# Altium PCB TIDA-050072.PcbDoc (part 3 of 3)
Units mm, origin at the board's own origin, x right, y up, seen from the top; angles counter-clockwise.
Board outline 125.73 x 87.63 mm, 2 copper layers (Top Layer, Bottom Layer), stack 1.575 mm thick; 105 components, 63 nets, 347 pads, 390 vias.
Unrouted connection lines stored in the file: 6.
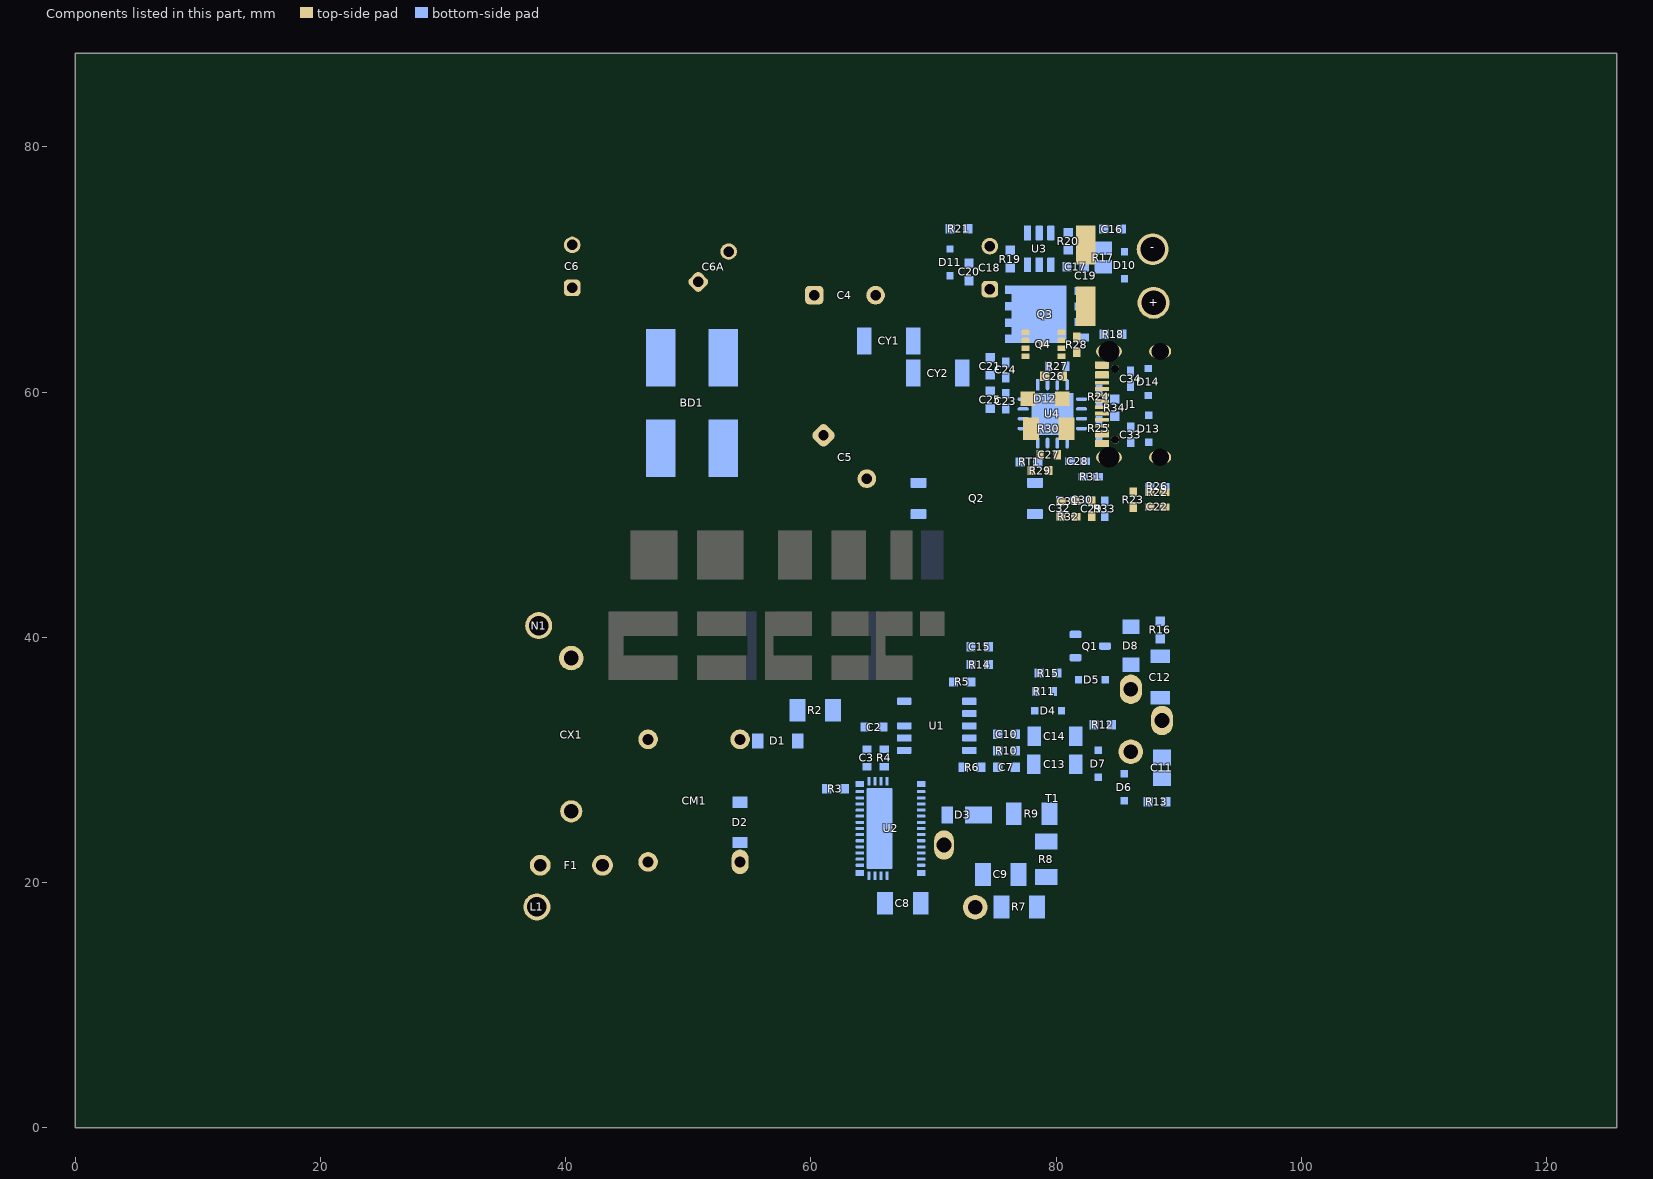
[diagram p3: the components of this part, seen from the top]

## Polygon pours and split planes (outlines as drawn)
NetBD1_3 on Top Layer "TOP_LAYER_NETBD1_3_P046" (solid, remove dead copper, pour order 46): 54.5,55.375 54.029,55.846 51.171,55.846 50.7,55.375 50.7,44.713 54.5,44.712
NetBD1_2 on Top Layer "TOP_LAYER_NETBD1_2_P048" (solid, remove dead copper, pour order 48): 49.1,55.4 48.654,55.846 45.746,55.846 45.275,55.375 45.275,44.7 49.1,44.7
NetBD1_1 on Top Layer "TOP_LAYER_NETBD1_1_P050" (solid, remove dead copper, pour order 50): 51.025,69.95 46.95,69.95 46.3,69.3 36.7,69.3 36.2,68.8 36.2,66.35 36.675,65.875 45,65.875 45.3,65.575 45.3,58.125 45.95,57.475 48.602,57.475 48.95,57.823 48.95,65.325 48.975,65.325 51.9,68.25 51.9,69.1 51.05,69.95
NetBD1_1 on Top Layer "TOP_LAYER_NETBD1_1_P052" (solid, remove dead copper, pour order 52): 58.925,69.1 60.607,69.1 61.4,68.307 61.4,57.925 62,57.325 62,56.166 60.1,54.266 60.1,44.712 57.325,44.712 57.3,44.738 57.3,55.75 58.375,56.825 58.375,65.462 58.375,68.55
G on Top Layer "TOP_LAYER_G_P056" (solid, remove dead copper, pour order 56): 56.75,58.05 56.175,57.475 51.975,57.475 51.625,57.825 51.625,65.725 53.475,67.575 53.475,69.8 51.75,71.525 45.5,71.525 44.85,70.875 36.775,70.875 36.25,71.4 36.25,73.85 36.7,74.3 68.25,74.3 69.1,73.45 69.1,67.8 67.3,66 67.3,51.95 64.5,49.15 64.5,44.712 61.682,44.712 61.682,53.557 63.625,55.5 63.625,58.05 63,58.675 63,68.9 61.225,70.675 58.275,70.675 56.75,69.15
Vo on Top Layer "TOP_LAYER_VO_P057" (solid, remove dead copper, pour order 57): 74.575,69.625 77.65,69.625 78.3,68.975 83.554,68.975 84.815,67.714 84.815,65.4 79.79,65.4 79.475,65.085 79.475,62.35 79.295,62.17 77.53,62.17 73.75,65.95 73.75,68.8
VBUS on Top Layer "TOP_LAYER_VBUS_P058" (solid, remove dead copper, pour order 58): 80.1,64.425 80.1,58.95 80.25,58.8 81.21,58.8 81.8,58.21 81.8,57 82.5,56.3 84.225,56.3 84.225,56.9 83.11,56.9 82.95,57.06 82.95,60.925 83.125,61.1 84.25,61.1 84.25,61.701 83.024,61.701 82.85,61.875 82.85,62.475 82.725,62.6 82.3,62.6 81.975,62.925 81.975,63.5 81.375,63.5 80.775,64.1 80.775,64.425
SGND on Top Layer "TOP_LAYER_SGND_P059" (solid, remove dead copper, pour order 59): 85.075,74.15 71.35,74.15 70.35,73.15 70.35,66.1 74.3,62.15 74.3,60.725 75.525,59.5 75.525,57.875 77.325,56.075 78.675,56.075 78.675,58.075 78.35,58.4 78.35,59.825 79.45,60.925 79.45,61.675 77.35,61.675 73.375,65.65 73.375,69.275 74.175,70.075 84.525,70.075 85.025,69.575 88.7,69.575 89.3,70.175 89.3,72.5 88.625,73.175 86.925,73.175 86.425,72.675 85.9,72.675 85.425,73.15 85.425,73.825 85.4,73.825
RTN on Top Layer "TOP_LAYER_RTN_P063" (solid, remove dead copper, pour order 63): 83.175,62.029 83.175,63.869 83.637,64.331 84.956,64.331 85.862,63.425 86.441,63.425 86.75,63.116 86.75,62.675 87.422,62.003 88.984,62.003 89.265,61.723 89.265,56.3 89.037,56.072 87.5,56.072 86.675,55.247 86.675,53.919 87.25,53.344 87.25,52.711 87.014,52.475 84.112,52.475 83.791,52.797 83.791,53.801 83.441,54.15 82.125,54.15 80.481,55.794 80.481,57.925 81.495,57.925 81.495,56.926 82.321,56.1 84.357,56.1 84.8,56.543 84.8,61.615 84.515,61.9 83.304,61.9
G on Top Layer "TOP_LAYER_G_P028" (solid, remove dead copper, pour order 28): 61.7,38.5 61.7,35.85 58.35,32.5 57.225,32.5 56.6,31.875 56.6,20.65 57.5,19.75 66.693,19.75 68.575,21.632 68.575,27.066 67.916,27.725 64.75,27.725 64.55,27.525 64.55,25.75 64.15,25.35 60.6,25.35 60.6,29.675 65.225,34.3 65.225,35.95 64.7,36.475 64.7,38.5
G on Top Layer "TOP_LAYER_G_P073" (solid, remove dead copper, pour order 73): 68.45,24.349 68.58,24.479 68.58,27.94 68.07,28.45 67.035,28.45 66.17,27.585 66.17,25.32 67.141,24.349
G on Top Layer "TOP_LAYER_G_P067" (solid, remove dead copper, pour order 67): 72.5,40.3 72.5,37.692 69.758,34.95 66.9,34.95 63.475,31.525 61.615,29.665 61.615,26.232 62.05,25.797 63.742,25.8 64.15,26.208 64.15,27.7 64.675,28.225 65.95,28.225 66.575,28.85 69.95,28.85 70.753,28.047 82.528,28.047 87.375,23.2 88.75,23.2 89.675,24.125 89.675,28.952 87.25,31.377 87.25,39.925 85.95,41.225 73.425,41.225
NetD3_1 on Top Layer "TOP_LAYER_NETD3_1_P066" (solid, remove dead copper, pour order 66): 72.912,26.537 81.538,26.537 85.95,22.125 85.95,19.108 83.804,16.962 78.063,16.962 73,22.025 73,24.375 72.575,24.8 72.575,26.2
NetBD1_1 on Top Layer "TOP_LAYER_NETBD1_1_P016" (solid, remove dead copper, pour order 16): 56.25,37.536 56.25,35.4 55.8,34.95 49.85,34.95 49.1,34.2 49.1,17.65 50,16.75 71.525,16.75 71.95,17.175 71.95,18.8 71.525,19.225 68.325,19.225 67.35,18.25 54.15,18.25 51.85,20.55 51.85,33.3 52.6,34.05 57.65,34.05 60.1,36.5 60.1,37.536
NetCM1_1 on Top Layer "TOP_LAYER_NETCM1_1_P014" (solid, remove dead copper, pour order 14): 46.7,28.8 47.55,27.95 47.55,20.55 47,20 45.8,20 45.3,20.5 45.3,25.4 44.45,26.25 42,26.25 41.8,26.05 41.8,25.7 42,25.5 44,25.5 44.45,25.05 44.45,20.9 43.8,20.25 42.45,20.25 42.1,20.6 42.1,22.9 39.2,25.8 39.2,28.05 39.95,28.8
NetF1_2 on Top Layer "TOP_LAYER_NETF1_2_P012" (solid, remove dead copper, pour order 12): 39,21.55 38.05,22.5 36.75,22.5 36.2,21.95 36.2,17.25 36.65,16.8 38.6,16.8 39,17.2
NetCM1_2 on Top Layer "TOP_LAYER_NETCM1_2_P008" (solid, remove dead copper, pour order 8): 40.6,42.15 41.75,41 41.75,34.95 42.65,34.05 46.75,34.05 47.55,33.25 47.55,31.25 46.8,30.5 37.85,30.5 36.55,31.8 36.55,35.8 38.3,37.55 38.3,38.5 36.4,40.4 36.4,41.65 36.9,42.15
NetBD1_2 on Bottom Layer "BOTTOM_LAYER_NETBD1_2_P030" (solid, remove dead copper, pour order 30): 49.1,55.4 48.654,55.846 45.746,55.846 45.275,55.375 45.275,44.7 49.1,44.7
NetBD1_3 on Bottom Layer "BOTTOM_LAYER_NETBD1_3_P032" (solid, remove dead copper, pour order 32): 54.5,55.375 54.029,55.846 51.171,55.846 50.7,55.375 50.7,44.713 54.5,44.712
G on Bottom Layer "BOTTOM_LAYER_G_P034" (solid, remove dead copper, pour order 34): 51.65,57.475 51.65,64.325 52.375,65.05 55.925,65.05 56.8,64.175 56.8,58.1 56.175,57.475
NetBD1_1 on Bottom Layer "BOTTOM_LAYER_NETBD1_1_P036" (solid, remove dead copper, pour order 36): 48.95,57.45 45.975,57.45 45.3,58.125 45.3,61.15 45.3,65.575 45,65.875 36.675,65.875 36.2,66.35 36.2,68.8 36.7,69.3 46.3,69.3 46.95,69.95 51.05,69.95 51.9,69.1 58.55,69.1 60.95,69.1 62,68.05 62,56.166 60.1,54.266 60.1,44.712 57.325,44.712 57.3,44.738 57.3,55.75 58.375,56.825 58.375,65.375 57.1,66.65 50.275,66.65 48.95,65.325
G on Bottom Layer "BOTTOM_LAYER_G_P038" (solid, remove dead copper, pour order 38): 61.682,53.557 63.6,55.475 63.6,68.757 61.682,70.675 52.6,70.675 51.75,71.525 46.325,71.525 45.675,70.875 36.775,70.875 36.25,71.4 36.25,73.85 36.7,74.3 68.25,74.3 69.1,73.45 69.1,70.475 64.925,66.3 64.925,59.3 65.575,58.65 65.575,50.225 64.5,49.15 64.5,44.712 61.682,44.712
RTN on Bottom Layer "BOTTOM_LAYER_RTN_P060" (solid, remove dead copper, pour order 60): 83.275,63.675 83.275,61.361 83.661,60.975 85.325,60.975 85.64,61.29 87.26,61.29 88.2,60.35 88.2,57.375 87.125,56.3 85.8,56.3 85.1,55.6 83.525,55.6 83.2,55.275 83.2,54.472 83.807,53.865 89.19,53.865 89.75,54.425 89.75,64.275 89.275,64.75 87.35,64.75 86.6,64 83.6,64
Net+_1 on Bottom Layer "BOTTOM_LAYER_NET+_1_P061" (solid, remove dead copper, pour order 61): 83.25,70.139 86.661,70.139 87,69.8 88.825,69.8 89.375,69.25 89.375,66.15 88.89,65.665 83.015,65.665 82.725,65.375 81.525,65.375 81.525,68.575 82.75,68.575 83.25,69.075
Vo on Bottom Layer "BOTTOM_LAYER_VO_P062" (solid, remove dead copper, pour order 62): 80.85,68.7 75.975,68.7 75.2,69.475 72.9,69.475 72.9,65.175 74.311,63.764 80.614,63.764 80.85,64
SGND on Bottom Layer "BOTTOM_LAYER_SGND_P064" (solid, remove dead copper, pour order 64): 74.925,72.775 73.775,72.775 72.525,71.525 72.525,70.139 74.953,70.139 75.4,70.586 75.4,72.3
G on Bottom Layer "BOTTOM_LAYER_G_P072" (solid, remove dead copper, pour order 72): 75.785,41.975 84.439,41.975 85.025,41.389 85.025,37.5 86.95,35.575 86.95,34.063 86.662,33.775 83.141,33.775 79.603,37.313 78.925,37.313 76.562,34.95 75.975,34.95 75.161,35.764 75.161,41.351
G on Bottom Layer "BOTTOM_LAYER_G_P071" (solid, remove dead copper, pour order 71): 66.925,36.525 68.51,36.525 68.975,36.06 69.575,35.459 69.575,30.666 69.966,30.275 70.984,30.275 71.95,31.262 71.95,32.868 70.775,34.043 70.775,35.089 70.775,36.994 71.094,37.313 72.148,37.313 72.7,36.761 72.7,36.06 73.45,36.06 73.45,40.886 73.186,41.15 71.75,41.15 71.35,40.75 71.35,38.533 71.194,38.378 66.925,38.378
NetF1_2 on Bottom Layer "BOTTOM_LAYER_NETF1_2_P068" (solid, remove dead copper, pour order 68): 39,21.55 38.05,22.5 36.75,22.5 36.2,21.95 36.2,17.25 36.65,16.8 38.6,16.8 39,17.2
NetCM1_1 on Bottom Layer "BOTTOM_LAYER_NETCM1_1_P069" (solid, remove dead copper, pour order 69): 46.7,28.8 47.55,27.95 47.55,20.55 47,20 45.8,20 45.3,20.5 45.3,25.4 44.45,26.25 42,26.25 41.8,26.05 41.8,25.7 42,25.5 44,25.5 44.45,25.05 44.45,20.9 43.8,20.25 42.45,20.25 42.1,20.6 42.1,22.9 39.2,25.8 39.2,28.05 39.95,28.8
NetCM1_2 on Bottom Layer "BOTTOM_LAYER_NETCM1_2_P070" (solid, remove dead copper, pour order 70): 40.6,42.15 41.75,41 41.75,35.25 44.125,32.875 46.9,32.875 47.55,32.225 47.55,31.25 46.8,30.5 37.85,30.5 36.55,31.8 36.55,35.8 38.3,37.55 38.3,38.5 36.4,40.4 36.4,41.65 36.9,42.15
G on Bottom Layer "BOTTOM_LAYER_G_P065" (solid, remove dead copper, pour order 65): 76.275,29.025 76.525,28.775 79.875,28.775 80.5,29.4 80.5,31.675 78.85,33.325 77.025,33.325 76.275,32.575
NetBD1_1 on Bottom Layer "BOTTOM_LAYER_NETBD1_1_P026" (solid, remove dead copper, pour order 26): 71.225,19.225 73.35,21.35 74.65,21.35 74.675,21.325 74.675,19.625 75.475,18.825 75.475,17.075 75.15,16.75 68.75,16.75 68.325,17.175 68.325,18.975 68.575,19.225
NetD3_1 on Bottom Layer "BOTTOM_LAYER_NETD3_1_P020" (solid, remove dead copper, pour order 20): 72.575,26.2 72.575,24.8 73,24.375 73,23.05 73.4,22.65 76.8,22.65 77.187,23.038 77.188,26.537 72.912,26.537
NetD3_2 on Bottom Layer "BOTTOM_LAYER_NETD3_2_P018" (solid, remove dead copper, pour order 18): 71.575,26.199 69.892,26.208 69.5,26.6 69.5,27.325 69.3,27.525 68.725,27.525 68.65,27.45 68.65,21.35 68.725,21.275 70.775,21.275 71.575,22.075
G on Bottom Layer "BOTTOM_LAYER_G_P006" (solid, remove dead copper, pour order 6): 60.25,25.5 59.8,25.95 59.8,26.9 59.575,27.125 57.75,27.125 57.15,26.525 57.15,18.125 57.875,17.4 64.725,17.4 65.186,17.861 66.65,17.861 66.65,27.661 64.55,27.661 64.55,25.6 64.45,25.5
NetBD1_3 on Bottom Layer "BOTTOM_LAYER_NETBD1_3_P004" (solid, remove dead copper, pour order 4): 50.7,37.6 50.7,36.461 53.4,33.761 53.4,31.2 53.95,30.65 55.8,30.65 56.1,30.95 56.1,32.6 55.55,33.15 55.55,37.6
NetBD1_2 on Bottom Layer "BOTTOM_LAYER_NETBD1_2_P002" (solid, remove dead copper, pour order 2): 43.5,35.9 44.95,34.45 47.5,34.45 49.4,32.55 49.4,22.325 51.563,20.162 54.362,20.162 54.95,20.75 54.95,23.65 54.55,24.05 53.1,24.05 51.8,25.35 51.8,26.55 51.8,33.05 49.1,35.75 49.1,38.2 43.5,38.2

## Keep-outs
Keep-Out Layer:
  text ".Layer_Name" at 14.656,-21.806 h1.52

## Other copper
Top Layer:
  text ".Layer_Name" at 14.656,-21.806 h1.52
Bottom Layer:
  text ".Layer_Name" at 14.656,-21.806 h1.52

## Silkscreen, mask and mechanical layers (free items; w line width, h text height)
Top Overlay:
  text ".Layer_Name" at 14.656,-21.806 h1.52
Bottom Overlay:
  lines w0.2: 75.375,39.3 75.375,41.275 76.225,42.125 89.05,42.125 89.65,41.525 89.65,38 ; 65.8,54.325 65.8,59.863 71.469,59.863 71.469,54.311 65.814,54.311 65.8,54.325
  text "**" at 89.544,60.78 h0.8 r90
  text "**" at 71.471,58.212 h0.8 r90
  text ".Layer_Name" at 14.656,-21.806 h1.52
Top Paste:
  text ".Layer_Name" at 14.656,-21.806 h1.52
Bottom Paste:
  text ".Layer_Name" at 14.656,-21.806 h1.52
Top Solder:
  text ".Layer_Name" at 14.656,-21.806 h1.52
  text ".Layer_Name" at 14.656,-21.806 h1.52
Bottom Solder:
  text ".Layer_Name" at 14.656,-21.806 h1.52
Drill Guide:
  text ".Layer_Name" at 14.656,-21.806 h1.52
M1 Board Outline:
  circle w0.15: c91,36 r1
  circle w0.15: c91,25.5 r1
  circle w0.15: c76,15.5 r1
  circle w0.15: c54,15.5 r1
  circle w0.15: c35,24 r1
  circle w0.15: c35,35 r1
  circle w0.15: c69.5,43.5 r1
  circle w0.15: c91,52 r1
  circle w0.15: c91,69 r1
  circle w0.15: c35,67 r1
  circle w0.15: c73,75.5 r1
  circle w0.15: c58,75.5 r1
  circle w0.15: c60.9,43.5 r1
  circle w0.15: c49.9,43.5 r1
  lines w0.15: 35.994,16.5 90,16.5 90,42.5 35.994,42.5 ; 36,16.5 36,42.5 ; 36,65.5 45,65.5 45,44.5 54.7,44.5 54.7,48 57.1,48 57.1,44.5 64.7,44.5 64.7,48 66.3,48 66.3,44.5 71,44.5 71,49 90,49 90,74.5 70.2,74.5 70.2,64 69.4,64 69.4,74.5 36,74.5 36,65.5 ; 44.8,38.6 44.8,40 54.8,40 54.8,38.6 44.8,38.6 ; 57,38.6 64.8,38.6 64.8,40 57,40 57,38.6 ; 66.2,38.6 71.1,38.6 71.1,40 66.2,40 66.2,38.6
  lines w0.254: 0.125,0 0.125,87.63 125.73,87.63 125.73,0 0.125,0
  text ".Layer_Name" at 14.656,-21.806 h1.52
M2 Board Dimensions:
  rectangle: 0,-6.985 3.175,-3.81
  rectangle: 3.175,-10.16 12.7,-6.985
  lines w0.178: 0,-6.985 25.4,-6.985 ; 3.175,-10.16 3.175,-3.81 ; 6.35,-10.16 6.35,-3.81 ; 12.7,-10.16 12.7,-3.81 ; 19.05,-10.16 19.05,-3.81 ; 0,-10.16 25.4,-10.16 25.4,-3.81 0,-3.81 0,-10.16
  text ".Layer_Name" at 14.656,-21.806 h1.52
M3 3D STEP Top:
  text ".Layer_Name" at 14.656,-21.806 h1.52
M4 3D STEP Bottom:
  text ".Layer_Name" at 14.656,-21.806 h1.52
M5 Assembly Top:
  lines w0.254: -7.417,-23.626 160.223,-23.626 ; -7.417,-18.462 160.274,-18.462 ; -7.417,-13.297 -7.417,-28.791 94.31,-28.791 160.274,-28.791 160.274,-13.297 -7.404,-13.297 -7.404,-28.791 32.614,-28.791 ; 55.194,-28.791 55.194,-13.297 ; 87.376,-18.462 87.376,-13.297 ; 108.712,-18.462 108.712,-13.297 ; 124.511,-28.956 124.511,-23.804
  text "COMPONENTS MARKED 'DNP' SHOULD NOT BE POPULATED." at 29.299,-8.09 h1.52
  text "ASSEMBLY VARIANT:" at 29.286,-11.024 h1.52
  text ".VariantName" at 55.601,-11.024 h1.52
  text "PCB VIEWED FROM TOP SIDE" at -5.804,-16.654 h1.52
  text "BOARD #:" at 57.099,-16.654 h1.52
  text ".PRJ_Number" at 70.955,-16.654 h1.52
  text "REV:" at 92.405,-16.654 h1.52
  text ".PCB_Rev" at 99.809,-16.654 h1.52
  text "SVN REV:" at 113.69,-16.654 h1.52
  text ".VersionControl_RevNumber" at 126.543,-16.654 h1.52
  text "TID #:" at 57.099,-21.819 h1.52
  text ".TID" at 70.955,-21.819 h1.52
  text "PLOT NAME =" at -5.804,-27.034 h1.52
  text ".plot_File_Name" at 14.656,-27.034 h1.52
  text "GENERATED    :" at 57.15,-27.034 h1.52
  text ".Print_Date" at 79.235,-27.034 h1.52
  text ".Print_Time" at 97.752,-27.034 h1.52
  text "TEXAS INSTRUMENTS" at 129.87,-27.034 h1.52
M6 Assembly Bottom:
  lines w0.254: -7.429,-18.474 160.261,-18.474 ; -7.379,-23.639 160.261,-23.639 ; 28.334,-28.969 28.334,-23.817 ; 44.133,-18.474 44.133,-13.31 ; 65.468,-18.474 65.468,-13.31 ; 97.65,-28.804 97.65,-13.31 ; 120.231,-28.804 160.249,-28.804 160.249,-13.31 -7.429,-13.31 -7.429,-28.804 58.534,-28.804 160.261,-28.804 160.261,-13.31
  text "COMPONENTS MARKED 'DNP' SHOULD NOT BE POPULATED." at 154.991,-8.077 h1.52
  text ".VariantName" at 128.473,-11.024 h1.52
  text "ASSEMBLY VARIANT:" at 154.864,-11.024 h1.52
  text ".VersionControl_RevNumber" at 26.302,-16.667 h1.52
  text "SVN REV:" at 39.154,-16.667 h1.52
  text ".PCB_Rev" at 53.035,-16.667 h1.52
  text "REV:" at 60.439,-16.667 h1.52
  text ".PRJ_Number" at 81.89,-16.667 h1.52
  text "BOARD #:" at 95.745,-16.667 h1.52
  text "PCB VIEWED FROM BOTTOM SIDE" at 158.648,-16.667 h1.52
  text ".TID" at 81.89,-21.831 h1.52
  text "TID #:" at 95.745,-21.831 h1.52
  text "TEXAS INSTRUMENTS" at 22.974,-27.047 h1.52
  text ".Print_Time" at 55.093,-27.047 h1.52
  text ".Print_Date" at 73.609,-27.047 h1.52
  text "GENERATED    :" at 95.694,-27.047 h1.52
  text ".plot_File_Name" at 138.189,-27.047 h1.52
  text "PLOT NAME =" at 158.648,-27.047 h1.52
M9 Title Sheet:
  drawing of 57 lines, arcs and shapes, not listed
  text "1" at 18.792,204.127 h1.78
  text "2" at 82.182,204.127 h1.78
  text "3" at 145.411,204.127 h1.78
  text "4" at 209.08,204.127 h1.78
  text "5" at 272.555,204.127 h1.78
  text "6" at 336.182,204.127 h1.78
  text "A" at -10.579,175.095 h1.78
  text "A" at 365.341,175.095 h1.78
  text "B" at -10.579,114.643 h1.78
  text "B" at 365.341,114.643 h1.78
  text "C" at -10.579,54.318 h1.78
  text "C" at 365.341,54.318 h1.78
  text "PROJECT TITLE:" at 288.125,7.048 h1.14
  text ".PRJ_Title" at 289.395,3.662 h1.78
  text "DESIGNED FOR:" at 288.125,-0.597 h1.14
  text ".PRJ_Customer" at 289.395,-4.153 h1.78
  text "D" at -10.579,-5.88 h1.78
  text "D" at 365.341,-5.88 h1.78
  text "FILE NAME:" at 288.125,-8.217 h1.14
  text ".PCB_File_Name_No_Path" at 289.395,-11.265 h1.78
  text "Texas Instruments (TI) and/or its licensors do not warrant the accuracy or completeness of this specification" at 161.9,-15.376 h1.14
  text "ENGINEER:" at 288.125,-15.583 h1.14
  text "LAYOUT BY:" at 326.352,-15.583 h1.14
  text "or any information contained therein. TI and/or its licensors do not warrant that this design will meet" at 160.757,-18.237 h1.14
  text ".PRJ_Engineer" at 289.395,-19.52 h1.78
  text ".PCB_Layout" at 327.635,-19.52 h1.78
  text "the specifications, will be suitable for your application or fit for any particular purpose, or will operate in" at 160.757,-21.099 h1.14
  text ".Layer_Name" at 14.656,-21.806 h1.52
  text "ALTIUM DESIGNER VERSION:" at 326.352,-23.457 h1.14
  text "an implementation. TI and/or its licensors do not warrant that the design is production worthy. You should" at 160.757,-23.961 h1.14
  text "completely validate and test your design implementation to confirm the system functionality for your application." at 161.9,-26.822 h1.14
  text ".print_Scale" at 289.395,-26.843 h1.78
  text ".Application_BuildNumber" at 327.635,-26.843 h1.78
  text "1" at 18.792,-32.093 h1.78
  text "2" at 82.182,-32.093 h1.78
  text "3" at 145.411,-32.093 h1.78
  text "4" at 209.08,-32.093 h1.78
  text "5" at 272.555,-32.093 h1.78
  text "6" at 336.182,-32.093 h1.78
M10 Fab Notes:
  drawing of 189 lines, arcs and shapes, not listed
  text "DESIGN INFORMATION" at 314.503,161.447 h1.52
  text "MIN. TRACK WIDTH:" at 298.131,158.091 h1.52
  text "8" at 325.976,158.091 h1.52
  text "MIL" at 329.907,158.091 h1.52
  text "7.874" at 321.75,155 h1.52
  text "MIN. CLEARANCE:" at 298.131,154.938 h1.52
  text "MIL" at 329.907,154.938 h1.52
  text "MIN. VIA PAD SIZE:" at 298.131,151.785 h1.52
  text "24" at 325.214,151.785 h1.52
  text "MIL" at 329.907,151.785 h1.52
  text "0.05mm (2MIL)" at 315.784,148.486 h1.52
  text "MINIMUM ANNULAR RING" at 289.769,148.277 h1.52
  text "EXTERNAL" at 333.768,148.277 h1.52
  text "PER" at 294.849,145.48 h1.52
  text "IPC-D-275 CLASS 2 LEVEL C" at 300.437,145.48 h1.52
  text "MIL, HOLES" at 338.238,142.928 h1.52
  text "+/-" at 328.27,142.709 h1.52
  text "+/-" at 349.961,142.709 h1.52
  text "REGISTRATION TOLERANCES:" at 289.769,142.682 h1.52
  text "METAL" at 320.243,142.682 h1.52
  text "5" at 334.879,142.683 h1.52
  text "3" at 356.037,142.683 h1.52
  text "MIL" at 358.99,142.682 h1.52
  text "HOLE SIZE TOLERANCE (UNLESS OTHERWISE SPECIFIED):" at 289.769,140.185 h1.52
  text "+/-" at 349.961,140.112 h1.52
  text "3" at 356.037,140.085 h1.52
  text "MIL" at 358.99,140.085 h1.52
  text "MATERIAL:" at 287.87,136.589 h1.52
  text "FR-4 High Tg" at 312.926,133.324 h1.52
  text "X" at 309.257,133.122 h1.52
  text "FR-408" at 298.563,133.007 h1.52
  text "OTHER" at 336.358,133.007 h1.52
  text "62 MIL (1.6mm) +/-10%" at 306.694,129.374 h1.52
  text "X" at 303.643,129.312 h1.52
  text "THICKNESS:" at 289.769,129.165 h1.52
  text "OTHER" at 339.33,129.165 h1.52
  text "TOLERANCE:" at 289.769,125.652 h1.52
  text "X" at 311.314,125.652 h1.52
  text "ANSI IPC-6012 TYPE 3 CLASS 2" at 315.836,125.652 h1.52
  text "OTHER +/-" at 315.835,121.989 h1.52
  text "BOW & TWIST:" at 289.769,118.302 h1.52
  text "X" at 311.314,118.302 h1.52
  text "ANSI IPC-6012 TYPE 3 CLASS 2" at 315.836,118.302 h1.52
  text "OTHER +/-" at 315.835,114.576 h1.52
  text "DRILLING:" at 287.87,111.258 h1.52
  text "NC_DRILL FILES" at 332.599,108.586 h1.52
  text "REFERENCE:" at 289.769,108.486 h1.52
  text "X" at 306.463,108.484 h1.52
  text "AS SHOWN" at 310.984,108.486 h1.52
  text "X" at 329.348,108.486 h1.52
  text "OTHER" at 340.168,104.873 h1.52
  text "PTH COPPER THICKNESS:" at 289.761,104.783 h1.52
  text "X" at 318.697,104.783 h1.52
  text "20-30 um" at 321.948,104.783 h1.52
  text "BOARD FINISH:" at 287.87,101.034 h1.52
  text "SILKSCREEN:" at 291.812,98.237 h1.52
  text "X" at 316.14,98.237 h1.52
  text "TOP" at 319.112,98.237 h1.52
  text "X" at 329.094,98.237 h1.52
  text "BOTTOM" at 332.091,98.237 h1.52
  text "SILKSCREEN COLOR:" at 291.812,94.295 h1.52
  text "X" at 316.115,94.295 h1.52
  text "WHITE" at 319.112,94.295 h1.52
  text "OTHER" at 332.091,94.295 h1.52
  text "X" at 319.442,90.652 h1.52
  text "GREEN" at 322.439,90.652 h1.52
  text "OTHER" at 338.136,90.652 h1.52
  text "SOLDER RESIST COLOR:" at 291.812,90.477 h1.52
  text "X" at 319.442,86.734 h1.52
  text "MATTE" at 322.439,86.734 h1.52
  text "SEMI-GLOSS" at 338.125,86.717 h1.52
  text "IMMERSION GOLD (ENIG)" at 314.819,82.345 h1.52
  text "ENEPIG" at 348.793,82.162 h1.52
  text "SURFACE FINISH:" at 287.87,82.136 h1.52
  text "X" at 310.298,82.136 h1.52
  text "IMM. TIN/SILVER OR EQUIV" at 296.24,78.649 h1.52
  text "OTHER" at 332.599,78.549 h1.52
  text "ARRAY/PANEL:" at 287.87,74.602 h1.52
  text "CUT AND TRIM PER M1 BOARD OUTLINE" at 314.819,74.393 h1.52
  text "N.C. ROUTE" at 314.819,70.94 h1.52
  text "X" at 332.295,70.94 h1.52
  text "V. SCORE" at 336.816,70.94 h1.52
  text "CERTIFICATION:" at 287.87,67.66 h1.52
  text "MATERIALS AND WORKMANSHIP FOR ALL PCBS" at 306.285,67.66 h1.52
  text "TO MEET OR EXCEED THE REQUIREMENTS OF:" at 306.285,65.271 h1.52
  text "X" at 297.078,62.003 h1.52
  text "ANSI IPC-A-600F CLASS ->" at 300.329,62.003 h1.52
  text "X" at 342.188,62.003 h1.52
  text "2" at 344.982,62.003 h1.52
  text "1" at 336.981,61.965 h1.52
  text "3" at 353.973,61.965 h1.52
  text "X" at 317.702,58.252 h1.52
  text "RoHS" at 320.953,58.252 h1.52
  text "OTHER" at 337.321,58.252 h1.52
  text "PER ORDER" at 347.407,58.252 h1.52
  text "ALL BOARDS MUST MEET OR EXCEED UL94-V0 REQUIREMENTS." at 288.569,54.345 h1.52
  text "PCB MUST BEAR THE UL94V-0 UL REGISTERED MATERIAL ID NUMBER" at 288.569,51.397 h1.52
  text "ADDITIONAL REQUIREMENTS:" at 287.87,47.094 h1.52
  text "MICROSECTION:" at 289.769,44.373 h1.52
  text "YES" at 312.775,44.373 h1.52
  text "REQUIRED" at 334.657,40.707 h1.52
  text "BARE BOARD ELEC. TEST:" at 289.769,40.634 h1.52
  text "NONE" at 322.935,40.634 h1.52
  text "X" at 331.66,40.634 h1.52
  text "PER ORDER" at 349.693,40.634 h1.52
  text "XX MIL VIAS REQUIRE NON-CONDUCTIVE FILL AND PLANARIZE" at 294.04,35.428 h1.5
  text "XX MIL VIAS REQUIRE CONDUCTIVE FILL AND PLANARIZE" at 294.243,32.787 h1.52
  text "OUTER XX MIL TRACES REQUIRE 50 OHM SINGLE-ENDED IMPEDANCE" at 294.218,28.637 h1.47
  text "LAYER 2 & 3 (INNER LAYERS) XX MIL WIDE, XX MIL SPACE / TRACES REQUIRE 100 OHM DIFFERENTIAL IMPEDANCE" at 294.015,22.65 h1.52
  text ".Layer_Name" at 14.656,-21.806 h1.52
M11 Gerber Information:
  lines w0.254: -7.417,-23.626 160.223,-23.626 ; -7.417,-18.462 160.274,-18.462 ; -7.417,-13.297 -7.417,-28.791 94.31,-28.791 160.274,-28.791 160.274,-13.297 -7.404,-13.297 -7.404,-28.791 32.614,-28.791 ; 55.194,-28.791 55.194,-13.297 ; 87.376,-18.462 87.376,-13.297 ; 108.712,-18.462 108.712,-13.297 ; 124.511,-28.956 124.511,-23.804
  text "ALL ARTWORK VIEWED FROM TOP SIDE" at -5.804,-16.654 h1.52
  text "BOARD #:" at 57.099,-16.654 h1.52
  text ".PRJ_Number" at 70.955,-16.654 h1.52
  text "REV:" at 92.405,-16.654 h1.52
  text ".PCB_Rev" at 99.809,-16.654 h1.52
  text "SVN REV:" at 113.69,-16.654 h1.52
  text ".VersionControl_RevNumber" at 126.543,-16.654 h1.52
  text "LAYER NAME =" at -5.804,-21.806 h1.52
  text "TID #:" at 57.099,-21.819 h1.52
  text ".TID" at 70.955,-21.819 h1.52
  text "PLOT NAME =" at -5.804,-27.034 h1.52
  text ".plot_File_Name" at 14.656,-27.034 h1.52
  text "GENERATED    :" at 57.15,-27.034 h1.52
  text ".Print_Date" at 79.235,-27.034 h1.52
  text ".Print_Time" at 97.752,-27.034 h1.52
  text "TEXAS INSTRUMENTS" at 129.87,-27.034 h1.52
M12 Stackup:
  drawing of 191 lines, arcs and shapes, not listed
  text "Layer" at 249.469,194.308 h1.52
  text "Name" at 259.88,194.308 h1.52
  text "Material" at 283.496,194.308 h1.52
  text "Thickness" at 305.334,194.308 h1.52
  text "Constant" at 321.84,194.308 h1.52
  text "Board Layer Stack" at 336.314,194.308 h1.52
  text "Top Overlay" at 259.88,191.26 h1.52
  text "Top Solder" at 259.88,188.212 h1.52
  text "Solder Resist" at 283.496,188.212 h1.52
  text "0.40mil" at 305.334,188.212 h1.52
  text "3.5" at 321.84,188.212 h1.52
  text "1" at 249.469,185.164 h1.52
  text "Top Layer" at 259.88,185.164 h1.52
  text "1.40mil" at 305.334,185.164 h1.52
  text "Dielectric1" at 259.88,182.116 h1.52
  text "FR-4 High Tg" at 283.496,182.116 h1.52
  text "59.20mil" at 305.334,182.116 h1.52
  text "4.8" at 321.84,182.116 h1.52
  text "2" at 249.469,179.068 h1.52
  text "Bottom Layer" at 259.88,179.068 h1.52
  text "1.40mil" at 305.334,179.068 h1.52
  text "Bottom Solder" at 259.88,176.02 h1.52
  text "Solder Resist" at 283.496,176.02 h1.52
  text "0.40mil" at 305.334,176.02 h1.52
  text "3.5" at 321.84,176.02 h1.52
  text "Bottom Overlay" at 259.88,172.972 h1.52
  text ".Layer_Name" at 14.656,-21.806 h1.52
M13 Component Bodies Top:
  text ".Layer_Name" at 14.656,-21.806 h1.52
M14 Component Bodies Bottom:
  text ".Layer_Name" at 14.656,-21.806 h1.52
M15 Courtyards Top:
  rectangle: 83.47,35.29 91.2,38.6
  lines w0.15: 56.173,21 56.173,76.75 ; 69.365,17.84 69.365,72.37
  lines w0.2: 71.1,38.6 91.629,38.6
  lines w1.2: 66.329,35.825 68.839,35.825 ; 67.729,28.175 69.598,28.175 70.253,27.519
  lines w1.5: 37.25,70.05 42.125,70.05 ; 46.625,70.675 51.5,70.675 52.275,69.9 60.9,69.9 62.2,68.6 62.2,67.05 62.2,58.3 62.8,57.7 62.8,55.975 ; 48.35,17.6 48.35,32.65 ; 49.9,36.05 49.9,43.95 ; 49.9,44 49.9,50.9 ; 50.275,65.45 52.7,67.875 52.7,70.825 ; 51.1,35.7 55.2,35.7 ; 51.9,33.3 56,33.3 ; 52.6,32.95 52.6,20.875 53.625,19.85 55.45,19.85 ; 55.025,19.025 67.011,19.025 67.993,20.007 68.984,20.007 69.25,20.273 69.25,24.079 70.754,25.583 ; 55.825,21 55.825,33.075 ; 56.75,33.3 58,33.3 60.9,36.2 60.9,42.65 ; 57.55,61.625 57.55,68.8 58.5,69.75 ; 60.9,42.85 60.9,47.3
  lines w3: 38.005,24.545 38.205,24.545 40.55,22.2 40.55,19.2
  lines w6: 71,60.95 71,59.654 72.4,58.254 72.4,50.732 75.432,47.7
  text ".Layer_Name" at 14.656,-21.806 h1.52
M16 Courtyards Bottom:
  lines w1: 74.04,22.125 76.55,22.125
  lines w1.2: 52.75,29.964 56.217,29.964 57.15,30.897 57.15,32.7 ; 55.7,25.9 55.7,26.9 58.8,30 59.75,30 61.05,31.3 ; 56.4,35.8 56.485,35.715 68.429,35.715 68.935,35.208 68.935,33.945 ; 62.476,32.193 63.15,32.867 63.15,34.259 ; 63.941,33.825 66.303,33.825 ; 67.377,19.9 69.888,19.9 ; 67.604,28.9 69.575,28.9 70.475,28 ; 71.694,27.3 82.9,27.3 ; 71.97,24.4 72.3,24.07 72.3,21.709
  lines w1.5: 38.825,70.175 38.9,70.1 46,70.1 46.65,70.75 ; 42.6,41.35 42.6,35.6 44.55,33.65 47.2,33.65 48.6,32.25 48.6,21.9 49,21.5 ; 45.501,56.625 54.625,56.625 ; 47.05,70.725 51.4,70.725 52.2,69.925 58.25,69.925 61.3,69.925 62.6,68.625 ; 49.9,36.05 52.6,33.35 52.6,25.7 53.4,24.9 54.85,24.9 55.7,24.05 55.7,21.088 ; 51.325,65.875 55.775,65.875 ; 56.3,37.124 56.3,41.574 ; 56.35,37.802 56.35,42.252 ; 56.925,65.75 57.575,65.1 57.575,58.2 ; 60.9,45.625 60.9,53.925 62.825,55.85 62.825,66.874
  lines w2.5: 67.4,58.825 66.35,59.875 66.35,65.725 68.025,67.4
  lines w6: 68.7,56.05 70.7,56.05 72.513,54.237 72.513,51.385 ; 73.142,50.745 74.366,49.521 74.366,47.25
  text ".Layer_Name" at 14.656,-21.806 h1.52
Drill Drawing:
  circle w0.254: c136.238,83.156 r0.421
  circle w0.254: c136.238,83.156 r0.702
  lines w0.254: 135.537,54.035 136.94,54.035 136.94,55.438 135.537,55.438 135.537,54.035 ; 135.537,57.894 136.238,57.193 136.94,57.894 136.238,58.596 135.537,57.894 ; 135.537,61.754 136.94,61.754 136.238,60.35 135.537,61.754 ; 135.537,63.508 136.238,63.859 136.94,63.508 136.589,64.21 136.94,64.911 136.238,64.561 135.537,64.911 135.888,64.21 135.537,63.508 ; 135.537,67.017 135.888,67.017 136.238,66.666 136.589,67.017 136.94,67.017 136.589,67.367 136.94,67.718 136.589,67.718 136.238,68.069 135.888,67.718 135.537,67.718 135.888,67.367 135.537,67.017 ; 135.537,70.174 135.888,70.174 135.888,69.823 136.589,69.823 136.589,70.174 136.94,70.174 136.94,70.876 136.589,70.876 136.589,71.227 135.888,71.227 135.888,70.876 135.537,70.876 135.537,70.174 ; 135.537,74.385 136.94,74.385 136.238,72.981 135.537,74.385 ; 135.537,76.139 136.94,76.139 136.94,77.542 135.537,77.542 135.537,76.139 ; 135.537,79.647 135.888,79.647 136.238,79.297 136.589,79.647 136.94,79.647 136.589,79.998 136.94,80.349 136.589,80.349 136.238,80.7 135.888,80.349 135.537,80.349 135.888,79.998 135.537,79.647 ; 135.537,85.612 135.537,85.963 135.888,86.314 135.537,86.665 135.537,87.016 135.888,87.016 136.238,86.665 136.589,87.016 136.94,87.016 136.94,86.665 136.589,86.314 136.94,85.963 136.94,85.612 136.589,85.612 136.238,85.963 135.888,85.612 135.537,85.612 ; 135.817,54.315 136.659,54.315 136.659,55.158 135.817,55.158 135.817,54.315 ; 135.817,61.473 136.659,61.473 136.238,60.631 135.817,61.473 ; 135.817,63.789 136.238,63.999 136.659,63.789 136.449,64.21 136.659,64.631 136.238,64.42 135.817,64.631 136.028,64.21 135.817,63.789 ; 135.817,79.788 136.028,79.788 136.238,79.577 136.449,79.788 136.659,79.788 136.449,79.998 136.659,80.209 136.449,80.209 136.238,80.419 136.028,80.209 135.817,80.209 136.028,79.998 135.817,79.788
  lines w0.305: 134.264,53.087 216.344,53.087 ; 134.264,87.822 216.344,87.822 ; 142.846,49.93 142.846,90.98 ; 151.279,49.93 151.279,90.98 ; 167.448,49.93 167.448,90.98 ; 174.03,49.93 174.03,90.98 ; 183.559,49.93 183.559,90.98 ; 201.957,49.93 201.957,90.98 ; 134.264,49.93 216.344,49.93 216.344,90.98 134.264,90.98 134.264,49.93
  text "Symbol" at 136.159,88.77 h1.83
  text "Quantity" at 143.793,88.77 h1.83
  text "Finished Hole Size" at 152.226,88.77 h1.83
  text "Plated" at 168.395,88.77 h1.83
  text "Hole Type" at 174.977,88.77 h1.83
  text "Drill Layer Pair" at 184.506,88.77 h1.83
  text "Hole Tolerance" at 202.904,88.77 h1.83
  text "2" at 143.793,85.612 h1.52
  text "25.59mil (0.650mm)" at 152.226,85.612 h1.52
  text "NPTH" at 168.395,85.612 h1.52
  text "Round" at 174.977,85.612 h1.52
  text "Top Layer - Bottom Layer" at 184.506,85.612 h1.52
  text "13" at 143.793,82.454 h1.52
  text "7.87mil (0.200mm)" at 152.226,82.454 h1.52
  text "PTH" at 168.395,82.454 h1.52
  text "Round" at 174.977,82.454 h1.52
  text "Top Layer - Bottom Layer" at 184.506,82.454 h1.52
  text "377" at 143.793,79.297 h1.52
  text "11.81mil (0.300mm)" at 152.226,79.297 h1.52
  text "PTH" at 168.395,79.297 h1.52
  text "Round" at 174.977,79.297 h1.52
  text "Top Layer - Bottom Layer" at 184.506,79.297 h1.52
  text "10" at 143.793,76.139 h1.52
  text "33.47mil (0.850mm)" at 152.226,76.139 h1.52
  text "PTH" at 168.395,76.139 h1.52
  text "Round" at 174.977,76.139 h1.52
  text "Top Layer - Bottom Layer" at 184.506,76.139 h1.52
  text "4" at 143.793,72.981 h1.52
  text "35.43mil (0.900mm)" at 152.226,72.981 h1.52
  text "PTH" at 168.395,72.981 h1.52
  text "Round" at 174.977,72.981 h1.52
  text "Top Layer - Bottom Layer" at 184.506,72.981 h1.52
  text "2" at 143.793,69.823 h1.52
  text "41.34mil (1.050mm)" at 152.226,69.823 h1.52
  text "PTH" at 168.395,69.823 h1.52
  text "Round" at 174.977,69.823 h1.52
  text "Top Layer - Bottom Layer" at 184.506,69.823 h1.52
  text "7" at 143.793,66.666 h1.52
  text "47.24mil (1.200mm)" at 152.226,66.666 h1.52
  text "PTH" at 168.395,66.666 h1.52
  text "Round" at 174.977,66.666 h1.52
  text "Top Layer - Bottom Layer" at 184.506,66.666 h1.52
  text "2" at 143.793,63.508 h1.52
  text "62.99mil (1.600mm)" at 152.226,63.508 h1.52
  text "PTH" at 168.395,63.508 h1.52
  text "Round" at 174.977,63.508 h1.52
  text "Top Layer - Bottom Layer" at 184.506,63.508 h1.52
  text "2" at 143.793,60.35 h1.52
  text "78.74mil (2.000mm)" at 152.226,60.35 h1.52
  text "PTH" at 168.395,60.35 h1.52
  text "Round" at 174.977,60.35 h1.52
  text "Top Layer - Bottom Layer" at 184.506,60.35 h1.52
  text "2" at 143.793,57.193 h1.52
  text "55.12mil (1.400mm)" at 152.226,57.193 h1.52
  text "PTH" at 168.395,57.193 h1.52
  text "Slot" at 174.977,57.193 h1.52
  text "Top Layer - Bottom Layer" at 184.506,57.193 h1.52
  text "2" at 143.793,54.035 h1.52
  text "66.93mil (1.700mm)" at 152.226,54.035 h1.52
  text "PTH" at 168.395,54.035 h1.52
  text "Slot" at 174.977,54.035 h1.52
  text "Top Layer - Bottom Layer" at 184.506,54.035 h1.52
  text "423 Total" at 143.793,50.877 h1.52
  text "Slot definitions :" at 136.159,48.667 h1.52
  text "Routed Path Length" at 147.607,48.667 h1.52
  text "= Calculated from tool start centre position to tool end centre position." at 161.317,48.667 h1.52
  text "Hole Length" at 147.607,47.404 h1.52
  text "= Routed Path Length + Tool Size = Slot length as defined in the PCB layout" at 156.242,47.404 h1.52
  text ".Layer_Name" at 14.656,-21.806 h1.52
M17 Embedded Cavity:
  text ".Layer_Name" at 14.656,-21.806 h1.52
M18 Embedded Assembly:
  text ".Layer_Name" at 14.656,-21.806 h1.52
M19 Embedded Keepout:
  text ".Layer_Name" at 14.656,-21.806 h1.52

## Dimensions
36,74.5 to 45,44.5 on M2 Board Dimensions
90,16.5 to 90,42.5 on M2 Board Dimensions
36,16.5 to 90,16.5 on M2 Board Dimensions
0,-10.16 to 25.4,-10.16 on M2 Board Dimensions
0,0 to 0,87.63 on M2 Board Dimensions
0,0 to 125.73,0 on M2 Board Dimensions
